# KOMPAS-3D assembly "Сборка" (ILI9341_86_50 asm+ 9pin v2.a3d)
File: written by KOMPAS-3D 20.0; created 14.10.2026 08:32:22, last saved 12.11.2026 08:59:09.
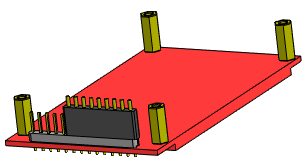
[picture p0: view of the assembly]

Document properties: Полное имя файла: D:\myProjects\Progect_esp32\box_compas\монитор\ILI9341_86_50 asm+ 9pin v2.a3d

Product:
- Part/product: Сборка
    Масса: 0.0882585
  - Component [detail]: Деталь  | Масса: 0.00180884; source file: ..\разъемы\pls_14.m3d
  - Component [detail]: Деталь  | Масса: 0.0790697; source file: ILI9341_86_50.m3d
  - Component [detail]: Деталь  | Масса: 0.00276261; source file: ..\разъемы\pbs_9.m3d
  - Component [detail]: Деталь  | qty 4  | Масса: 0.00115433; source file: ..\прочее\PCHSS-11.m3d

Referenced files in D:\myProjects\Progect_esp32\box_compas\монитор\: ILI9341_86_50.m3d
Referenced files in D:\myProjects\Progect_esp32\box_compas\разъемы\: pls_14.m3d, pbs_9.m3d
Referenced files in D:\myProjects\Progect_esp32\box_compas\прочее\: PCHSS-11.m3d
Referenced files in D:\RicWork\Project-EPS32\box_compas\прочее\: PCHSS-11.m3d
